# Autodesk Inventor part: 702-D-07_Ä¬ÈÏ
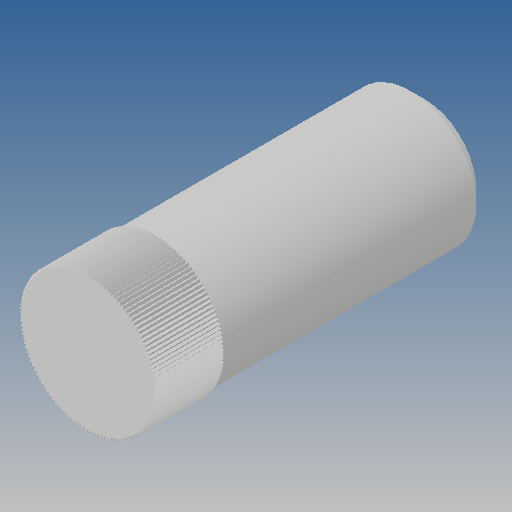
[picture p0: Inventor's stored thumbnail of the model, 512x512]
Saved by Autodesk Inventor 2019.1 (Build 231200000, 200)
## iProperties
Created: 2010-06
Part Number: 702-D-07_Ä¬ÈÏ
Material: Ogólny
Document SubType Name: Modeling
Designer: CADENGINEERING4
Density: 1 g/cm^3
Appearance: Domyślna
Author: CADENGINEERING4
Revision Number: ÈÎºÎ
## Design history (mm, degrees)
feature "NONE"
node "Bryła1"
